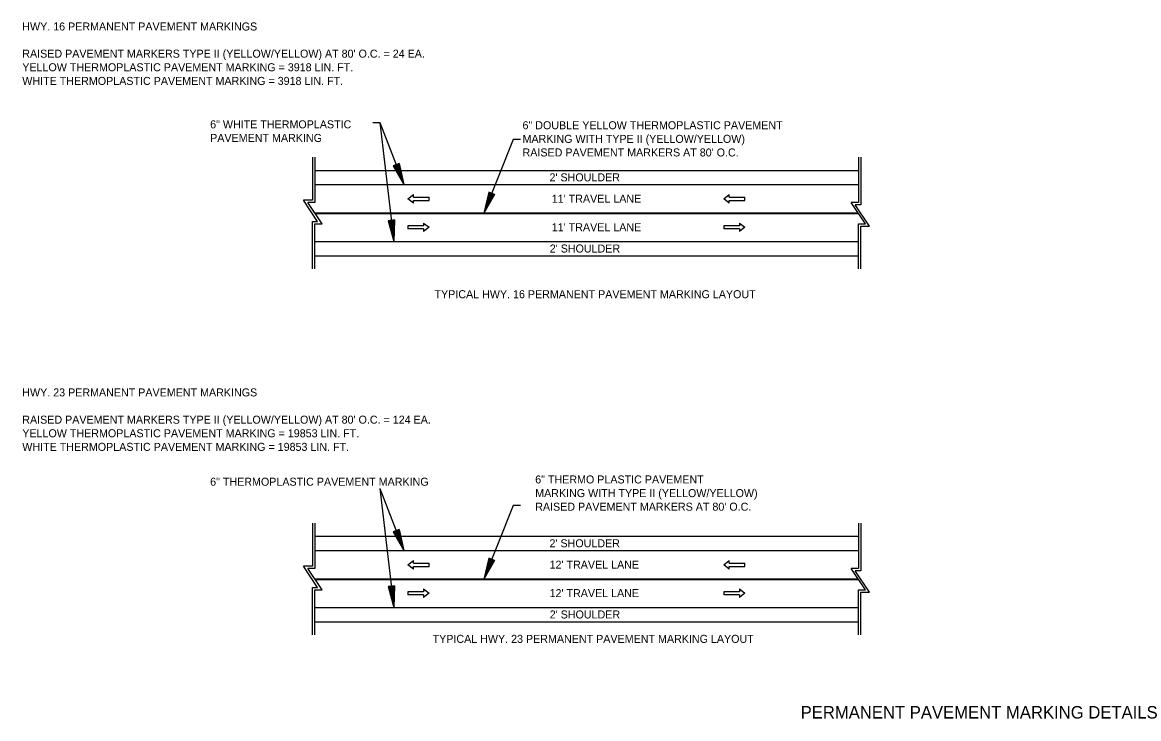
# Model space of a CAD drawing. Extents: x 2261938 to 2263136, y -3124572 to -3124216.
# Drawn here: x 2262466.8 to 2262623.7, y -3124313.5 to -3124215.6 of the extents above; entities that cross this region are included whole.
import ezdxf

# ---------------------------------------------------------------- set-up
doc = ezdxf.new("R2010")
doc.units = 0
for name, color, linetype in [('Default', 7, 'Continuous'), ('R_Draft', 7, 'Continuous'), ('SHET_Border-Text', 7, 'Continuous')]:
    doc.layers.add(name, color=color, linetype=linetype)

msp = doc.modelspace()

# ---------------------------------------------------------------- linework, layer by layer
at = {"layer": 'Default'}
for p, q in [((2262516.05, -3124229.73), (2262517.05, -3124229.73)), ((2262517.05, -3124229.73), (2262520.4, -3124238.45)), ((2262517.05, -3124229.73), (2262519, -3124246.45)), ((2262535.8, -3124232.09), (2262531.64, -3124242.45)), ((2262536.8, -3124232.09), (2262535.8, -3124232.09)), ((2262507.59, -3124234.61), (2262507.59, -3124240.62)), ((2262507.92, -3124234.61), (2262507.92, -3124240.95)), ((2262519.75, -3124235.49), (2262518.91, -3124235.81)), ((2262518.91, -3124235.81), (2262520.4, -3124238.45)), ((2262518.98, -3124235.78), (2262520.22, -3124237.98)), ((2262519.05, -3124235.75), (2262520.04, -3124237.5)), ((2262519.12, -3124235.73), (2262519.86, -3124237.03)), ((2262519.19, -3124235.7), (2262519.68, -3124236.56)), ((2262519.26, -3124235.67), (2262519.5, -3124236.09)), ((2262519.39, -3124235.62), (2262519.5, -3124236.09)), ((2262519.46, -3124235.6), (2262519.68, -3124236.56)), ((2262519.53, -3124235.57), (2262519.86, -3124237.03)), ((2262519.6, -3124235.54), (2262520.04, -3124237.5)), ((2262519.68, -3124235.51), (2262520.22, -3124237.98)), ((2262519.75, -3124235.49), (2262520.4, -3124238.45)), ((2262584.31, -3124234.61), (2262584.31, -3124240.95)), ((2262584.65, -3124234.61), (2262584.65, -3124241.28)), ((2262507.92, -3124236.45), (2262584.31, -3124236.45)), ((2262507.92, -3124238.45), (2262584.31, -3124238.45)), ((2262508.3, -3124243.62), (2262506.3, -3124240.62)), ((2262507.59, -3124240.62), (2262506.3, -3124240.62)), ((2262520.97, -3124240.45), (2262521.75, -3124239.85)), ((2262521.75, -3124241.05), (2262520.97, -3124240.45)), ((2262521.75, -3124240.22), (2262521.75, -3124239.85)), ((2262521.75, -3124240.22), (2262523.96, -3124240.22)), ((2262521.75, -3124240.67), (2262523.96, -3124240.67)), ((2262521.75, -3124241.05), (2262521.75, -3124240.67)), ((2262523.96, -3124240.67), (2262523.96, -3124240.22)), ((2262532.34, -3124239.5), (2262531.64, -3124242.45)), ((2262533.18, -3124239.83), (2262531.64, -3124242.45)), ((2262532.41, -3124239.52), (2262531.83, -3124241.98)), ((2262533.11, -3124239.8), (2262531.83, -3124241.98)), ((2262532.49, -3124239.55), (2262532.02, -3124241.5)), ((2262533.04, -3124239.78), (2262532.02, -3124241.5)), ((2262532.55, -3124239.58), (2262532.21, -3124241.04)), ((2262532.97, -3124239.75), (2262532.21, -3124241.04)), ((2262533.18, -3124239.83), (2262532.34, -3124239.5)), ((2262532.63, -3124239.61), (2262532.4, -3124240.57)), ((2262532.9, -3124239.72), (2262532.4, -3124240.57)), ((2262532.7, -3124239.64), (2262532.59, -3124240.1)), ((2262532.83, -3124239.69), (2262532.59, -3124240.1)), ((2262565.38, -3124240.45), (2262566.16, -3124239.85)), ((2262566.16, -3124241.05), (2262565.38, -3124240.45)), ((2262566.16, -3124240.22), (2262566.16, -3124239.85)), ((2262566.16, -3124240.22), (2262568.37, -3124240.22)), ((2262566.16, -3124240.67), (2262568.37, -3124240.67)), ((2262566.16, -3124241.05), (2262566.16, -3124240.67)), ((2262568.37, -3124240.67), (2262568.37, -3124240.22)), ((2262507.92, -3124240.95), (2262506.92, -3124240.95)), ((2262508.92, -3124243.95), (2262506.92, -3124240.95)), ((2262584.31, -3124240.95), (2262583.31, -3124240.95)), ((2262585.31, -3124243.95), (2262583.31, -3124240.95)), ((2262585.87, -3124244.28), (2262583.87, -3124241.28)), ((2262584.65, -3124241.28), (2262583.87, -3124241.28)), ((2262507.59, -3124243.62), (2262508.3, -3124243.62)), ((2262507.59, -3124250.29), (2262507.59, -3124243.62)), ((2262507.89, -3124242.4), (2262584.28, -3124242.4)), ((2262507.92, -3124250.29), (2262507.92, -3124243.95)), ((2262507.92, -3124243.95), (2262508.92, -3124243.95)), ((2262519.1, -3124243.42), (2262518.2, -3124243.52)), ((2262518.2, -3124243.52), (2262519, -3124246.45)), ((2262518.28, -3124243.51), (2262518.94, -3124245.95)), ((2262518.36, -3124243.5), (2262518.88, -3124245.44)), ((2262518.43, -3124243.49), (2262518.82, -3124244.94)), ((2262518.51, -3124243.49), (2262518.76, -3124244.44)), ((2262518.58, -3124243.48), (2262518.71, -3124243.94)), ((2262518.72, -3124243.46), (2262518.71, -3124243.94)), ((2262518.8, -3124243.45), (2262518.76, -3124244.44)), ((2262518.87, -3124243.44), (2262518.82, -3124244.94)), ((2262518.95, -3124243.43), (2262518.88, -3124245.44)), ((2262519.02, -3124243.43), (2262518.94, -3124245.95)), ((2262519.1, -3124243.42), (2262519, -3124246.45)), ((2262523.18, -3124243.85), (2262523.18, -3124244.22)), ((2262523.18, -3124243.85), (2262523.96, -3124244.45)), ((2262567.59, -3124243.85), (2262567.59, -3124244.22)), ((2262567.59, -3124243.85), (2262568.37, -3124244.45)), ((2262584.31, -3124250.29), (2262584.31, -3124243.95)), ((2262584.31, -3124243.95), (2262585.31, -3124243.95)), ((2262523.18, -3124244.22), (2262520.97, -3124244.22)), ((2262520.97, -3124244.22), (2262520.97, -3124244.67)), ((2262523.18, -3124244.67), (2262520.97, -3124244.67)), ((2262523.96, -3124244.45), (2262523.18, -3124245.05)), ((2262523.18, -3124244.67), (2262523.18, -3124245.05)), ((2262567.59, -3124244.22), (2262565.38, -3124244.22)), ((2262565.38, -3124244.22), (2262565.38, -3124244.67)), ((2262567.59, -3124244.67), (2262565.38, -3124244.67)), ((2262568.37, -3124244.45), (2262567.59, -3124245.05)), ((2262567.59, -3124244.67), (2262567.59, -3124245.05)), ((2262584.65, -3124250.29), (2262584.65, -3124244.28)), ((2262584.65, -3124244.28), (2262585.87, -3124244.28)), ((2262507.92, -3124246.45), (2262584.31, -3124246.45)), ((2262507.92, -3124248.45), (2262584.31, -3124248.45)), ((2262517.05, -3124281.15), (2262520.4, -3124289.87)), ((2262517.05, -3124281.15), (2262519, -3124297.87)), ((2262535.8, -3124283.52), (2262531.64, -3124293.87)), ((2262536.8, -3124283.52), (2262535.8, -3124283.52)), ((2262507.59, -3124286.04), (2262507.59, -3124292.04)), ((2262507.92, -3124286.04), (2262507.92, -3124292.37)), ((2262584.31, -3124286.04), (2262584.31, -3124292.37)), ((2262584.65, -3124286.04), (2262584.65, -3124292.71)), ((2262507.92, -3124287.87), (2262584.31, -3124287.87)), ((2262519.75, -3124286.91), (2262518.91, -3124287.23)), ((2262518.91, -3124287.23), (2262520.4, -3124289.87)), ((2262518.98, -3124287.21), (2262520.22, -3124289.41)), ((2262519.05, -3124287.18), (2262520.04, -3124288.92)), ((2262519.12, -3124287.15), (2262519.86, -3124288.46)), ((2262519.19, -3124287.12), (2262519.68, -3124287.98)), ((2262519.26, -3124287.1), (2262519.5, -3124287.51)), ((2262519.39, -3124287.05), (2262519.5, -3124287.51)), ((2262519.46, -3124287.02), (2262519.68, -3124287.98)), ((2262519.53, -3124286.99), (2262519.86, -3124288.46)), ((2262519.6, -3124286.97), (2262520.04, -3124288.92)), ((2262519.68, -3124286.94), (2262520.22, -3124289.41)), ((2262519.75, -3124286.91), (2262520.4, -3124289.87)), ((2262507.92, -3124289.87), (2262584.31, -3124289.87)), ((2262532.34, -3124290.92), (2262531.64, -3124293.87)), ((2262532.41, -3124290.95), (2262531.83, -3124293.41)), ((2262532.49, -3124290.98), (2262532.02, -3124292.93)), ((2262532.55, -3124291.01), (2262532.21, -3124292.47)), ((2262533.18, -3124291.26), (2262532.34, -3124290.92)), ((2262532.63, -3124291.03), (2262532.4, -3124291.99)), ((2262508.3, -3124295.04), (2262506.3, -3124292.04)), ((2262507.59, -3124292.04), (2262506.3, -3124292.04)), ((2262507.92, -3124292.37), (2262506.92, -3124292.37)), ((2262508.92, -3124295.37), (2262506.92, -3124292.37)), ((2262520.97, -3124291.87), (2262521.75, -3124291.27)), ((2262521.75, -3124292.47), (2262520.97, -3124291.87)), ((2262521.75, -3124291.65), (2262521.75, -3124291.27)), ((2262521.75, -3124291.65), (2262523.96, -3124291.65)), ((2262521.75, -3124292.1), (2262523.96, -3124292.1)), ((2262521.75, -3124292.47), (2262521.75, -3124292.1)), ((2262523.96, -3124292.1), (2262523.96, -3124291.65)), ((2262533.18, -3124291.26), (2262531.64, -3124293.87)), ((2262533.11, -3124291.23), (2262531.83, -3124293.41)), ((2262533.04, -3124291.2), (2262532.02, -3124292.93)), ((2262532.97, -3124291.17), (2262532.21, -3124292.47)), ((2262532.9, -3124291.14), (2262532.4, -3124291.99)), ((2262532.7, -3124291.06), (2262532.59, -3124291.53)), ((2262532.83, -3124291.12), (2262532.59, -3124291.53)), ((2262565.38, -3124291.87), (2262566.16, -3124291.27)), ((2262566.16, -3124292.47), (2262565.38, -3124291.87)), ((2262566.16, -3124291.65), (2262566.16, -3124291.27)), ((2262566.16, -3124291.65), (2262568.37, -3124291.65)), ((2262566.16, -3124292.1), (2262568.37, -3124292.1)), ((2262566.16, -3124292.47), (2262566.16, -3124292.1)), ((2262568.37, -3124292.1), (2262568.37, -3124291.65)), ((2262584.31, -3124292.37), (2262583.31, -3124292.37)), ((2262585.31, -3124295.37), (2262583.31, -3124292.37)), ((2262507.95, -3124293.92), (2262584.35, -3124293.92)), ((2262585.87, -3124295.71), (2262583.87, -3124292.71)), ((2262584.65, -3124292.71), (2262583.87, -3124292.71)), ((2262507.59, -3124295.04), (2262508.3, -3124295.04)), ((2262507.59, -3124301.71), (2262507.59, -3124295.04)), ((2262507.92, -3124301.71), (2262507.92, -3124295.37)), ((2262507.92, -3124295.37), (2262508.92, -3124295.37)), ((2262519.1, -3124294.84), (2262518.2, -3124294.94)), ((2262518.2, -3124294.94), (2262519, -3124297.87)), ((2262518.28, -3124294.94), (2262518.94, -3124297.38)), ((2262518.36, -3124294.93), (2262518.88, -3124296.86)), ((2262518.43, -3124294.92), (2262518.82, -3124296.37)), ((2262518.51, -3124294.91), (2262518.76, -3124295.86)), ((2262518.58, -3124294.9), (2262518.71, -3124295.36)), ((2262518.72, -3124294.88), (2262518.71, -3124295.36)), ((2262518.8, -3124294.88), (2262518.76, -3124295.86)), ((2262518.87, -3124294.87), (2262518.82, -3124296.37)), ((2262518.95, -3124294.86), (2262518.88, -3124296.86)), ((2262519.02, -3124294.85), (2262518.94, -3124297.38)), ((2262519.1, -3124294.84), (2262519, -3124297.87)), ((2262523.18, -3124295.65), (2262520.97, -3124295.65)), ((2262520.97, -3124295.65), (2262520.97, -3124296.1)), ((2262523.18, -3124295.27), (2262523.18, -3124295.65)), ((2262523.18, -3124295.27), (2262523.96, -3124295.87)), ((2262567.59, -3124295.65), (2262565.38, -3124295.65)), ((2262565.38, -3124295.65), (2262565.38, -3124296.1)), ((2262567.59, -3124295.27), (2262567.59, -3124295.65)), ((2262567.59, -3124295.27), (2262568.37, -3124295.87)), ((2262584.31, -3124301.71), (2262584.31, -3124295.37)), ((2262584.31, -3124295.37), (2262585.31, -3124295.37)), ((2262584.65, -3124301.71), (2262584.65, -3124295.71)), ((2262584.65, -3124295.71), (2262585.87, -3124295.71)), ((2262523.18, -3124296.1), (2262520.97, -3124296.1)), ((2262523.96, -3124295.87), (2262523.18, -3124296.47)), ((2262523.18, -3124296.1), (2262523.18, -3124296.47)), ((2262567.59, -3124296.1), (2262565.38, -3124296.1)), ((2262568.37, -3124295.87), (2262567.59, -3124296.47)), ((2262567.59, -3124296.1), (2262567.59, -3124296.47)), ((2262507.92, -3124297.87), (2262584.31, -3124297.87)), ((2262507.92, -3124299.87), (2262584.31, -3124299.87))]:
    msp.add_line(p, q, dxfattribs=at)
at = {"layer": 'R_Draft'}
for p, q in [((2262507.95, -3124242.5), (2262584.35, -3124242.5)), ((2262507.89, -3124293.82), (2262584.28, -3124293.82))]:
    msp.add_line(p, q, dxfattribs=at)

# ---------------------------------------------------------------- texts
at = {"layer": 'Default'}
for s, p in [('HWY. 16 PERMANENT PAVEMENT MARKINGS', (2262466.78, -3124216.79)), ("RAISED PAVEMENT MARKERS TYPE II (YELLOW/YELLOW) AT 80' O.C. = 24 EA.", (2262466.78, -3124220.61)), ('YELLOW THERMOPLASTIC PAVEMENT MARKING = 3918 LIN. FT.', (2262466.78, -3124222.52)), ('WHITE THERMOPLASTIC PAVEMENT MARKING = 3918 LIN. FT.', (2262466.78, -3124224.44)), ('6" WHITE THERMOPLASTIC', (2262493.19, -3124230.54)), ('6" DOUBLE YELLOW THERMOPLASTIC PAVEMENT', (2262537.1, -3124230.67)), ('PAVEMENT MARKING', (2262493.19, -3124232.45)), ('MARKING WITH TYPE II (YELLOW/YELLOW)', (2262537.1, -3124232.58)), ("RAISED PAVEMENT MARKERS AT 80' O.C.", (2262537.1, -3124234.49)), ("2' SHOULDER", (2262540.89, -3124237.99)), ("11' TRAVEL LANE", (2262541.21, -3124240.99)), ("11' TRAVEL LANE", (2262541.21, -3124244.99)), ("2' SHOULDER", (2262540.92, -3124247.99)), ('TYPICAL HWY. 16 PERMANENT PAVEMENT MARKING LAYOUT', (2262524.73, -3124254.41)), ('HWY. 23 PERMANENT PAVEMENT MARKINGS', (2262466.78, -3124268.21)), ("RAISED PAVEMENT MARKERS TYPE II (YELLOW/YELLOW) AT 80' O.C. = 124 EA.", (2262466.78, -3124272.04)), ('YELLOW THERMOPLASTIC PAVEMENT MARKING = 19853 LIN. FT.', (2262466.78, -3124273.95)), ('WHITE THERMOPLASTIC PAVEMENT MARKING = 19853 LIN. FT.', (2262466.78, -3124275.86)), ('6" THERMOPLASTIC PAVEMENT MARKING', (2262493.19, -3124280.76)), ('6" THERMO PLASTIC PAVEMENT', (2262538.88, -3124280.44)), ('MARKING WITH TYPE II (YELLOW/YELLOW)', (2262538.88, -3124282.36)), ("RAISED PAVEMENT MARKERS AT 80' O.C.", (2262538.88, -3124284.27)), ("2' SHOULDER", (2262540.89, -3124289.41)), ("12' TRAVEL LANE", (2262540.9, -3124292.41)), ("12' TRAVEL LANE", (2262540.9, -3124296.41)), ("2' SHOULDER", (2262540.92, -3124299.41)), ('TYPICAL HWY. 23 PERMANENT PAVEMENT MARKING LAYOUT', (2262524.46, -3124302.84))]:
    msp.add_text(s, height=1.125, dxfattribs=at).set_placement(p)
at = {"layer": 'SHET_Border-Text'}
msp.add_text('PERMANENT PAVEMENT MARKING DETAILS', height=1.75, dxfattribs=at).set_placement((2262576.19, -3124313.47))

doc.saveas('drawing.dxf')
